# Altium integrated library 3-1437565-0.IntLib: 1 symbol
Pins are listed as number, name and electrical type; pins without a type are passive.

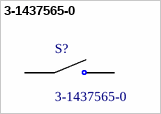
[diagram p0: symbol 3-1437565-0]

## 3-1437565-0
designator S?
Switch Tactile OFF (ON) SPST Round Button Gull Wing 0.05A 24VDC 1VA 9.18N SMD T/R; MF: TE Connectivity; MP: 314375650
footprint *SW_3-1437565-0
pins: 1 COM, 2 COM, 3 NO, 4 NO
